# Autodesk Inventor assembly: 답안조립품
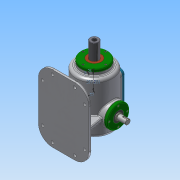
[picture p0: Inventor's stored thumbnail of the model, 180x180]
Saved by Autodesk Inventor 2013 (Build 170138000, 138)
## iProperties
Created: 2019-10
Part Number: 답안조립품
Document SubType Name: Assembly
Designer: Administrator
Mass: 7821.87 g
Surface Area: 4928.07 cm^2
Volume: 2176.15 cm^3
Density: 3.59435 g/cm^3
Author: Administrator
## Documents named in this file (17)
- C:\Users\Administrator\Desktop\391004V1037\답안조립품.iam
- C:\Users\Administrator\Desktop\391004V1037\본체.ipt
- C:\Users\Administrator\Desktop\391004V1037\가변스프링.ipt
- C:\Users\Administrator\Desktop\391004V1037\개스킷 A.ipt
- C:\Users\Administrator\Desktop\391004V1037\개스킷 B.ipt
- C:\Users\Administrator\Desktop\391004V1037\고정플레이트.ipt
- C:\Users\Administrator\Desktop\391004V1037\베어링 6205.ipt
- 베어링 6205.ipt
- C:\Users\Administrator\Desktop\391004V1037\볼트 M4x0.7.ipt
- C:\Users\Administrator\Desktop\391004V1037\부시.ipt
- C:\Users\Administrator\Desktop\391004V1037\상부커버.ipt
- C:\Users\Administrator\Desktop\391004V1037\슬라이드 커버.ipt
- C:\Users\Administrator\Desktop\391004V1037\슬라이드.ipt
- C:\Users\Administrator\Desktop\391004V1037\오일 실 25 38 8.ipt
- C:\Users\Administrator\Desktop\391004V1037\육각머리볼트 M4.ipt
- C:\Users\Administrator\Desktop\391004V1037\축 커버.ipt
- C:\Users\Administrator\Desktop\391004V1037\편심축.ipt
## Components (17 placed, 5 different names)
1. 가변스프링:1
2. 개스킷 A:1
3. 개스킷 B:1
4. 고정플레이트:1 — 플러쉬:1
5. 개스킷 B:2
6. M4x0.7:2
7. M4x0.7:4
8. M4x0.7:5
9. M4x0.7:6
10. M4x0.7:1
11. M4x0.7:7
12. M4x0.7:8
13. M4x0.7:9
14. M4x0.7:3
15. M4x0.7:10
16. M4x0.7:11
17. M4x0.7:12
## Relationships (1: Flush 1)
- 플러쉬:1 [Flush]: 고정플레이트:1
